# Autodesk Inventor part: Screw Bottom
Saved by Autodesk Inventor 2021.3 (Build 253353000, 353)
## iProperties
Created: 2022-08
Part Number: Screw Bottom
Material: Generic
Document SubType Name: Modeling
Designer: Administrator
Density: 1 g/cm^3
Appearance: Default
Title: Screw Bottom
Author: Administrator
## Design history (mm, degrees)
feature "Screw Bottom"
body "Solid1"
